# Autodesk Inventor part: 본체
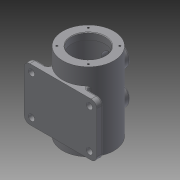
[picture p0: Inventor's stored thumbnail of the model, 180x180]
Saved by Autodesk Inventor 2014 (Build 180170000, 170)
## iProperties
Created: 2014-12
Part Number: 본체
Material: 일반
Document SubType Name: Modeling
Designer: Owner
Density: 1 g/cm^3
Appearance: 기본값
Mass: 477.153 g
Surface Area: 1041.15 cm^2
Volume: 477.153 cm^3
Author: Owner
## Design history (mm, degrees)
sketch "스케치1"
  geometry: C1 r 46 at (0, 0); 1 further point
  constraints: 1 centre point, 1 coincident
  dimensions: "d0" = 92 diameter of C1
extrude "돌출1" new body sketch "스케치1" distance "d1" = 140; taper "d2" = 0 deg
sketch "스케치2"
  geometry: C1 r 46 at (0, 0) reference; C2 r 30 at (0, 0)
  constraints: 1 centre point, 1 coincident
  dimensions: "d3" = 60 diameter of C2
extrude "돌출2" cut sketch "스케치2" stored distance "d4" = 140; taper "d5" = 0 deg
node "작업 평면1"
sketch "스케치3"
  geometry: C1 r 37.5 at (0, 0); 1 further point
  constraints: 1 centre point, 1 coincident
  dimensions: "d7" = 75 diameter of C1
extrude "돌출3" cut sketch "스케치3" distance "d8" = 116; taper "d9" = 0 deg
node "작업 평면2"
sketch "스케치4"
  geometry: L1 (-65, 110)-(65, 110); L2 (65, 110)-(65, 15); L3 (65, 15)-(-65, 15); L4 (-65, 15)-(-65, 110); L5 (46, 140)-(-46, 140) reference; L6 (-46, 0)-(46, 0) reference; 3 further points
  constraints: 8 end point, 2 midpoint, 2 parallel, 1 horizontal, 1 perpendicular, 1 vertical alignment
  dimensions: "d11" = 130 distance of L2.end L3.end; "d12" = 95 distance of L1.end L2.end; "d13" = 15 distance between parallel lines of L3 L6
extrude "돌출4" join sketch "스케치4" distance "d14" = 12; taper "d15" = 0 deg
node "작업 평면3"
sketch "스케치5"
  geometry: L1 (25.923, 110)-(-25.923, 110) reference; L2 (-25.923, 110)-(-25.923, 15) reference; L3 (-25.923, 15)-(25.923, 15) reference; L4 (25.923, 15)-(25.923, 110) reference; L5 (46, 140)-(-46, 140) reference; L6 (-46, 0)-(46, 0) reference; C1 r 20 at (0, 100); C2 r 20 at (0, 40); 2 further points
  constraints: 2 centre point, 1 midpoint, 1 vertical alignment
  dimensions: "d17" = 40 diameter of C1; "d18" = 40 diameter of C2; "d19" = 40 distance from line of C1.centre L5; "d20" = 60 distance of C2.centre C1.centre; "d21" = 40 distance from line of L6 C2.centre
extrude "돌출5" join sketch "스케치5" stored distance "d22" = 0; taper "d23" = 0 deg
sketch "스케치6"
  geometry: C1 r 20 at (0, 0) reference; 2 further points
  constraints: 1 coincident
sketch "스케치7"
  geometry: C1 r 20 at (0, 0) reference; 2 further points
  constraints: 1 coincident
hole "구멍1" sketch "스케치6" diameter "d24" = 25; stored, may be unused: countersink angle "d28" = 90 deg, drill point angle "d30" = 118 deg; dims "d25" = 6, "d26" = 30, "d27" = 8, "d29" = 8
hole "구멍2" sketch "스케치7" diameter "d31" = 25; stored, may be unused: countersink angle "d35" = 90 deg, drill point angle "d37" = 118 deg; dims "d32" = 6, "d33" = 30, "d34" = 8, "d36" = 8
sketch "스케치8"
  geometry: L1 (0, 0)-(28.284, 28.284); L2 (0, 0)-(40, 0); C1 r 46 at (0, 0) reference; 1 further point
  constraints: 4 end point, 1 coincident, 1 equal length, 1 horizontal
  dimensions: "d38" = 40 distance of L1.start L1.end; "d39" = 45 deg angle of L2 L1
hole "구멍3" sketch "스케치8" at (28.284, 28.284) diameter "d40" = 3.242; stored, may be unused: countersink angle "d44" = 90 deg, drill point angle "d46" = 118 deg; dims "d41" = 8, "d42" = 30, "d43" = 8, "d45" = 10
node "작업 평면4"
sketch "스케치9"
  geometry: L1 (25.923, -110)-(65, -110) reference; L2 (65, -110)-(65, -15) reference; C1 r 5.5 at (52, -97.5); 1 further point
  constraints: 1 centre point
  dimensions: "d50" = 11 diameter of C1; "d51" = 12.5 distance from line of C1.centre L1; "d52" = 13 distance from line of L2 C1.centre
extrude "돌출6" cut sketch "스케치9" distance "d53" = 12; taper "d54" = 0 deg
node "작업 평면5"
sketch "스케치10"
  geometry: L1 (65, -110)-(65, -15) reference; C1 r 5.5 at (52, -97.5) reference; 2 further points
  constraints: 1 other
  dimensions: "d55" = 35 vertical distance of point (57, -62.5) C1.centre; "d56" = 8 distance from line of point (57, -62.5) L1
feature "엠보싱1" sketch "스케치10" dims "d57" = 1, "d58" = 0
fillet "모깎기1" dims "d59" = 5
fillet "모깎기2" dims "d60" = 10
chamfer "모따기1" distance "d61" = 1; stored, may be unused: second distance "d62" = 2, angle "d63" = 45 deg
fillet "모깎기3" dims "d64" = 3
fillet "모깎기4" dims "d65" = 3
fillet "모깎기5" dims "d66" = 3
node "솔리드1"
pattern_circular "원형 패턴1" dims angle "d48" = 360 deg
mirror "대칭1"
mirror "대칭2"
mirror "대칭3"
node "투영된 루프1"
node "투영된 루프2"
other parameters: "d6" = 12, "d16" = 56
